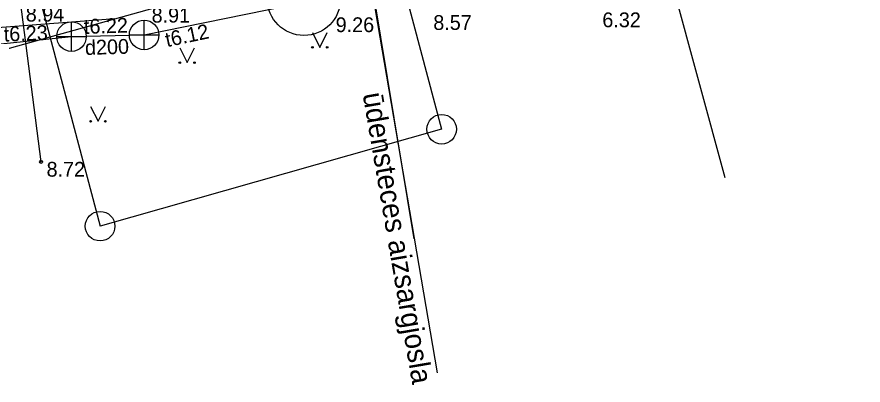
# Model space of a CAD drawing. Extents: x 496078 to 496285, y 304225 to 304369.
# Drawn here: x 496157.26 to 496185.87, y 304276.07 to 304288.53 of the extents above; entities that cross this region are included whole.
import ezdxf

# ---------------------------------------------------------------- set-up
doc = ezdxf.new("R2010")
doc.units = 0
for name, color, linetype in [('APGR_AIZS_####_####_#', 7, 'Continuous'), ('APGR_AIZS_####_TKST_#', 7, 'Continuous'), ('APGR_ELEM_####_####_#', 7, 'Continuous'), ('APGR_SARK_####_####_#', 7, 'Continuous'), ('CELI_CMAL_####_####_#', 7, 'Continuous'), ('ELEK_VADP_ZSPR_####_#', 7, 'Continuous'), ('Level 21', 7, 'Continuous'), ('Level 24', 7, 'Continuous'), ('RAMI_UZMR_####_####_#', 7, 'Continuous'), ('RELJ_AATZ_####_TKST_#', 7, 'Continuous'), ('RELJ_ELEM_####_####_#', 7, 'Continuous'), ('SKAN_DETP_SPDK_####_#', 7, 'Continuous'), ('SKAN_ELEM_####_####_#', 7, 'Continuous'), ('SKAN_ELEM_PAST_TKST_#', 7, 'Continuous'), ('SKAN_VADP_PAST_####_#', 7, 'Continuous'), ('SKAN_VADP_PAST_TKST_#', 7, 'Continuous'), ('TERT_ELEM_####_####_#', 7, 'Continuous')]:
    doc.layers.add(name, color=color, linetype=linetype)

msp = doc.modelspace()

# ---------------------------------------------------------------- linework, layer by layer
at = {"layer": 'APGR_AIZS_####_####_#'}
msp.add_lwpolyline([(496171.482, 304276.481), (496169.303, 304289.245), (496168.626, 304293.523), (496167.995, 304297.351), (496154.713, 304324.372)], dxfattribs=at)
at = {"layer": 'APGR_ELEM_####_####_#'}
for centre in [(496171.62, 304284.73), (496160.07, 304281.45)]:
    msp.add_circle(centre, 0.5, dxfattribs=at)
at = {"layer": 'APGR_SARK_####_####_#'}
for p, q in [((496169.119, 304294.152), (496171.616, 304284.732)), ((496157.839, 304289.874), (496160.071, 304281.452)), ((496171.616, 304284.732), (496160.071, 304281.452))]:
    msp.add_line(p, q, dxfattribs=at)
at = {"layer": 'CELI_CMAL_####_####_#'}
msp.add_lwpolyline([(496158.075, 304283.625), (496157.379, 304289.059), (496158.33, 304290.346), (496159.317, 304291.067), (496164.506, 304292.685), (496164.77, 304293.516), (496166.848, 304294.299), (496166.345, 304297.413), (496166.963, 304299.697), (496169.291, 304300.424), (496170.044, 304300.38), (496170.481, 304300.514)], dxfattribs=at)
at = {"layer": 'ELEK_VADP_ZSPR_####_#'}
msp.add_line((496155.19, 304288.074), (496160.572, 304288.474), dxfattribs=at)
at = {"layer": 'Level 21'}
msp.add_lwpolyline([(496176.843, 304299.089), (496181.199, 304283.099)], dxfattribs=at)
at = {"layer": 'Level 24'}
msp.add_lwpolyline([(496170.693, 304281.022), (496167.995, 304297.351)], dxfattribs=at)
at = {"layer": 'RAMI_UZMR_####_####_#'}
msp.add_line((496139.922, 304282.712), (496195.979, 304298.352), dxfattribs=at)
at = {"layer": 'RELJ_ELEM_####_####_#'}
msp.add_circle((496158.075, 304283.625), 0.05, dxfattribs=at)
at = {"layer": 'SKAN_DETP_SPDK_####_#'}
msp.add_circle((496166.963, 304289.14), 1.237, dxfattribs=at)
at = {"layer": 'SKAN_ELEM_####_####_#'}
for p, q in [((496159.104, 304287.366), (496159.104, 304288.366)), ((496161.56, 304287.422), (496161.56, 304288.422)), ((496158.604, 304287.866), (496159.604, 304287.866)), ((496161.06, 304287.922), (496162.06, 304287.922))]:
    msp.add_line(p, q, dxfattribs=at)
for centre in [(496159.104, 304287.866), (496161.56, 304287.922)]:
    msp.add_circle(centre, 0.5, dxfattribs=at)
at = {"layer": 'SKAN_VADP_PAST_####_#'}
for p, q in [((496161.56, 304287.922), (496167.053, 304289.039)), ((496153.848, 304287.327), (496159.104, 304287.866)), ((496159.104, 304287.866), (496161.56, 304287.922))]:
    msp.add_line(p, q, dxfattribs=at)
at = {"layer": 'TERT_ELEM_####_####_#'}
for p, q in [((496167.25, 304288), (496167.5, 304287.5)), ((496167.5, 304287.5), (496167.75, 304288)), ((496162.764, 304287.486), (496163.014, 304286.986)), ((496163.014, 304286.986), (496163.264, 304287.486)), ((496159.75, 304285.5), (496160, 304285)), ((496160, 304285), (496160.25, 304285.5))]:
    msp.add_line(p, q, dxfattribs=at)
for centre, radius in [((496167.25, 304287.5), 0.028), ((496167.75, 304287.5), 0.0263), ((496162.764, 304286.985), 0.028), ((496163.264, 304286.985), 0.0263), ((496159.75, 304285), 0.028), ((496160.25, 304285), 0.0263)]:
    msp.add_circle(centre, radius, dxfattribs=at)

# ---------------------------------------------------------------- texts
at = {"layer": 'APGR_AIZS_####_TKST_#'}
msp.add_text('ūdensteces aizsargjosla', height=0.7, rotation=279.6876, dxfattribs=at).set_placement((496168.948, 304285.918))
at = {"layer": 'RELJ_AATZ_####_TKST_#'}
for s, p in [(' 8.57', (496171.151, 304288.091)), (' 6.32', (496176.867, 304288.183)), (' 9.26', (496167.85, 304288.017)), (' 8.72', (496158.075, 304283.125))]:
    msp.add_text(s, height=0.5, dxfattribs=at).set_placement(p)
at = {"layer": 'SKAN_ELEM_PAST_TKST_#'}
for s, p in [(' 8.94', (496157.372, 304288.375)), (' 8.91', (496161.627, 304288.34))]:
    msp.add_text(s, height=0.5, dxfattribs=at).set_placement(p)
at = {"layer": 'SKAN_VADP_PAST_TKST_#'}
for s, rotation, p in [('t6.22', 1.8073, (496159.532, 304287.956)), ('t6.23', 2.4235, (496156.823, 304287.694)), ('t6.12', 11.8929, (496162.332, 304287.507)), ('d200', 1.8073, (496159.568, 304287.242))]:
    msp.add_text(s, height=0.5, rotation=rotation, dxfattribs=at).set_placement(p)

doc.saveas('drawing.dxf')
